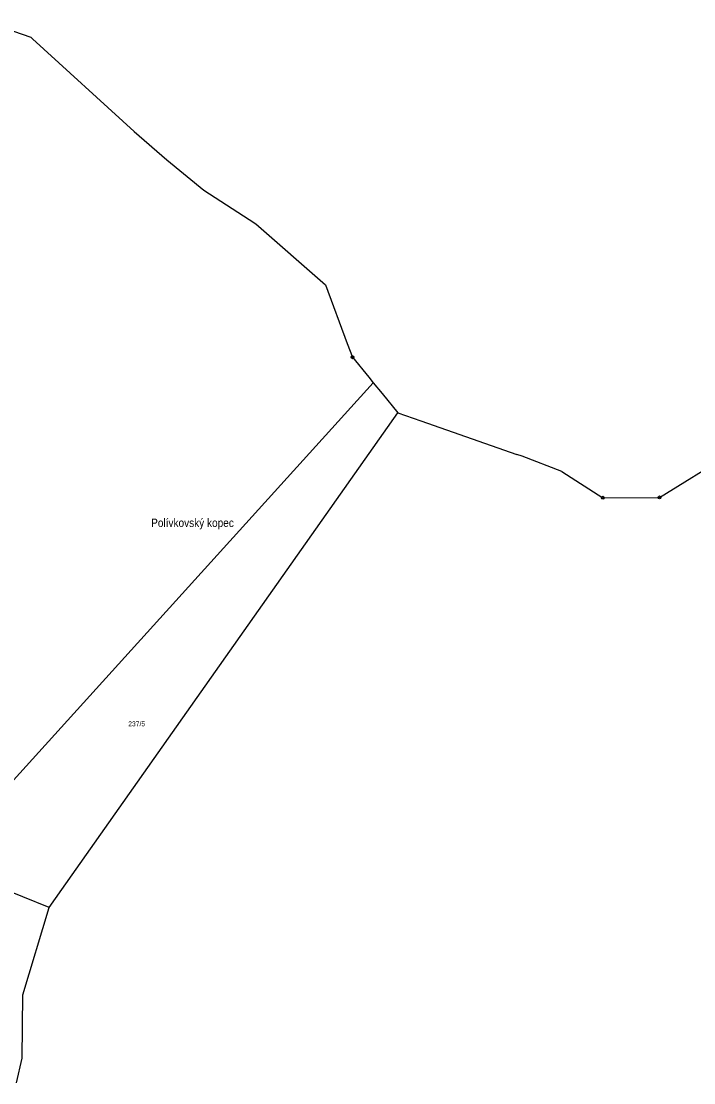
# Model space of a CAD drawing. Extents: x -632162 to -629607, y -1101195 to -1098670.
# Drawn here: x -631660 to -631426.6, y -1099061.4 to -1098693 of the extents above; entities that cross this region are included whole.
import ezdxf
from ezdxf.enums import TextEntityAlignment as Align

# ---------------------------------------------------------------- set-up
doc = ezdxf.new("R2010")
doc.units = 0
doc.header["$LTSCALE"] = 0.68
for name, color, linetype, lineweight in [('1', 7, 'Continuous', 25), ('7', 7, 'Continuous', 13), ('8', 7, 'Continuous', 25)]:
    doc.layers.add(name, color=color, linetype=linetype, lineweight=lineweight)
doc.layers.add('2', color=7, linetype='Continuous')

msp = doc.modelspace()

# ---------------------------------------------------------------- linework, layer by layer
at = {"layer": '1'}
for p, q in [((-631656.07, -1098699.15), (-631620.88, -1098731.3)), ((-631596.66, -1098751.65), (-631580.87, -1098761.81)), ((-631580.87, -1098761.81), (-631578.56, -1098763.29)), ((-631537.86, -1098818.43), (-631692.28, -1098988.88)), ((-631521.39, -1098831.65), (-631487.98, -1098843.32))]:
    msp.add_line(p, q, dxfattribs=at)
for points in [[(-631673.14, -1098693), (-631671.87, -1098693.28), (-631656.74, -1098698.54), (-631656.07, -1098699.15)], [(-631620.88, -1098731.3), (-631609.53, -1098741.09), (-631596.66, -1098751.65)], [(-631578.56, -1098763.29), (-631554.39, -1098784.44), (-631546.93, -1098804.81)], [(-631472.36, -1098849.3), (-631458.18, -1098858.36), (-631438.49, -1098858.24), (-631414.51, -1098843.5), (-631414.73, -1098828.35), (-631404.91, -1098793.61)], [(-631546.93, -1098804.81), (-631545.07, -1098809.6), (-631539.44, -1098816.49)], [(-631539.44, -1098816.49), (-631537.86, -1098818.43), (-631534.8, -1098822.17)], [(-631534.8, -1098822.17), (-631529.34, -1098828.87), (-631521.39, -1098831.65)], [(-631650.36, -1099000.53), (-631645.95, -1098994.28), (-631529.34, -1098828.87)], [(-631472.36, -1098849.3), (-631486.18, -1098843.95), (-631487.98, -1098843.32)], [(-631650.36, -1099000.53), (-631677.9, -1098989.47), (-631683.14, -1098989.26)], [(-631661.63, -1099061.36), (-631659.71, -1099052.82), (-631659.46, -1099030.83), (-631650.36, -1099000.53)]]:
    msp.add_lwpolyline(points, dxfattribs=at)
at = {"layer": '8'}
for centre, radius in [((-631545.07, -1098809.5999), 0.5), ((-631545.07, -1098809.5999), 0.0303), ((-631458.18, -1098858.3599), 0.5), ((-631458.18, -1098858.3599), 0.0303), ((-631438.49, -1098858.2399), 0.5), ((-631438.49, -1098858.2399), 0.0303)]:
    msp.add_circle(centre, radius, dxfattribs=at)

# ---------------------------------------------------------------- texts
at = {"layer": '2'}
msp.add_text('237/5', height=1.7, dxfattribs=at).set_placement((-631619.96, -1098937.66), align=Align.CENTER)
at = {"layer": '7', "width": 0.9}
msp.add_text('Polívkovský kopec', height=2.9, dxfattribs=at).set_placement((-631600.589, -1098868.49), align=Align.CENTER)

doc.saveas('drawing.dxf')
